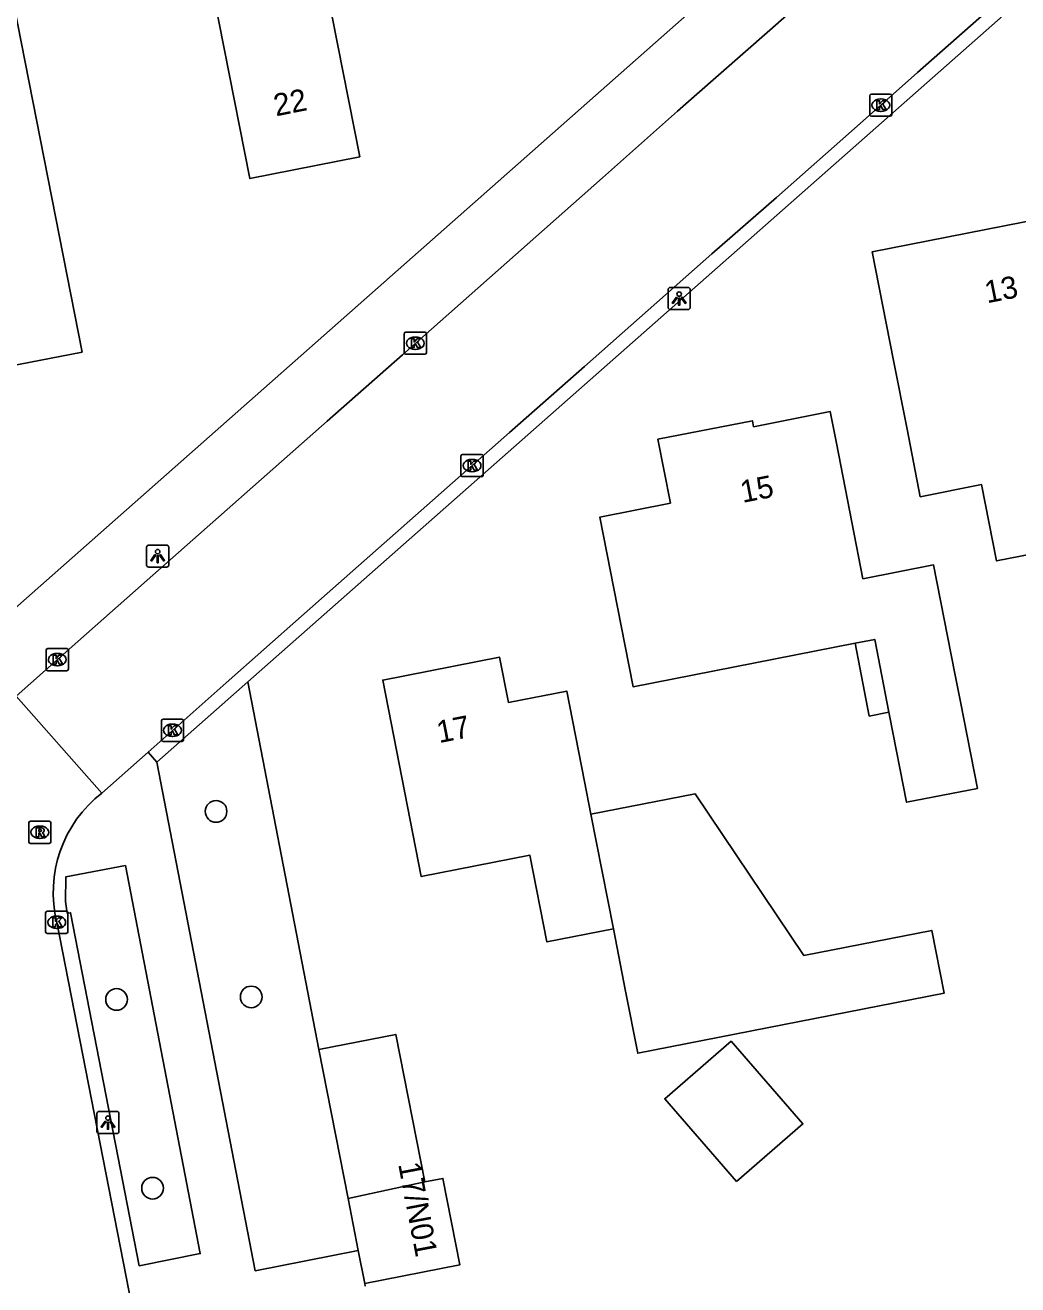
# Model space of a CAD drawing. Extents: x 157663 to 158496, y 379212 to 380934.
# Drawn here: x 158234.8 to 158279.6, y 380348.2 to 380405 of the extents above; entities that cross this region are included whole.
import ezdxf

# ---------------------------------------------------------------- set-up
doc = ezdxf.new("R2010")
doc.units = 0
for name, color, linetype in [('IMGEO_Boom', 7, 'Continuous'), ('IMGEO_Groenvoorziening', 7, 'Continuous'), ('IMGEO_Kolk', 7, 'Continuous'), ('IMGEO_Lichtpunt', 7, 'Continuous'), ('IMGEO_Pand', 7, 'Continuous'), ('IMGEO_Pand_nummerreeks', 7, 'Continuous'), ('IMGEO_Rijbaan_lokaal_open', 7, 'Continuous'), ('IMGEO_Rioolput', 7, 'Continuous'), ('IMGEO_Voetpad_open', 7, 'Continuous')]:
    doc.layers.add(name, color=color, linetype=linetype)

msp = doc.modelspace()

# ---------------------------------------------------------------- linework, layer by layer
at = {"layer": 'IMGEO_Boom'}
for centre in [(158243.442, 380369.576), (158238.959, 380361.095), (158245.027, 380361.208), (158240.581, 380352.586)]:
    msp.add_circle(centre, 0.489, dxfattribs=at)
at = {"layer": 'IMGEO_Groenvoorziening'}
msp.add_lwpolyline([(158248.079, 380358.837), (158244.872, 380375.418)], dxfattribs=at)
at = {"layer": 'IMGEO_Kolk'}
for p, q in [((158272.913, 380400.995), (158272.913, 380401.847)), ((158272.988, 380401.921), (158273.84, 380401.921)), ((158273.401, 380401.701), (158273.426, 380401.701)), ((158273.914, 380401.847), (158273.914, 380400.995)), ((158273.424, 380401.141), (158273.399, 380401.141)), ((158273.84, 380400.921), (158272.988, 380400.921)), ((158251.927, 380390.26), (158251.927, 380391.112)), ((158252.002, 380391.186), (158252.854, 380391.186)), ((158252.415, 380390.966), (158252.44, 380390.966)), ((158252.928, 380391.112), (158252.928, 380390.26)), ((158252.438, 380390.406), (158252.413, 380390.406)), ((158252.854, 380390.186), (158252.002, 380390.186)), ((158254.485, 380384.743), (158254.485, 380385.595)), ((158254.56, 380385.669), (158255.412, 380385.669)), ((158254.973, 380385.449), (158254.998, 380385.449)), ((158255.486, 380385.595), (158255.486, 380384.743)), ((158255.412, 380384.669), (158254.56, 380384.669)), ((158254.996, 380384.889), (158254.971, 380384.889)), ((158235.783, 380375.994), (158235.783, 380376.846)), ((158235.858, 380376.92), (158236.71, 380376.92)), ((158236.271, 380376.7), (158236.296, 380376.7)), ((158236.784, 380376.846), (158236.784, 380375.994)), ((158236.294, 380376.14), (158236.269, 380376.14)), ((158236.71, 380375.92), (158235.858, 380375.92)), ((158240.976, 380372.806), (158240.976, 380373.658)), ((158241.051, 380373.732), (158241.903, 380373.732)), ((158241.464, 380373.512), (158241.489, 380373.512)), ((158241.977, 380373.658), (158241.977, 380372.806)), ((158241.903, 380372.732), (158241.051, 380372.732)), ((158241.487, 380372.952), (158241.462, 380372.952)), ((158235.759, 380364.15), (158235.759, 380365.002)), ((158235.834, 380365.076), (158236.686, 380365.076)), ((158236.247, 380364.856), (158236.272, 380364.856)), ((158236.76, 380365.002), (158236.76, 380364.15)), ((158236.27, 380364.296), (158236.245, 380364.296)), ((158236.686, 380364.076), (158235.834, 380364.076))]:
    msp.add_line(p, q, dxfattribs=at)
for points in [[(158272.913, 380400.995), (158272.913, 380401.847)], [(158272.988, 380401.921), (158273.84, 380401.921)], [(158273.234, 380401.621), (158273.357, 380401.621), (158273.357, 380401.47), (158273.487, 380401.621), (158273.651, 380401.621), (158273.505, 380401.47), (158273.658, 380401.221), (158273.506, 380401.221), (158273.421, 380401.385), (158273.357, 380401.318), (158273.357, 380401.221), (158273.234, 380401.221), (158273.234, 380401.621)], [(158273.914, 380401.847), (158273.914, 380400.995)], [(158273.84, 380400.921), (158272.988, 380400.921)], [(158251.927, 380390.26), (158251.927, 380391.112)], [(158252.002, 380391.186), (158252.854, 380391.186)], [(158252.248, 380390.886), (158252.371, 380390.886), (158252.371, 380390.735), (158252.501, 380390.886), (158252.665, 380390.886), (158252.519, 380390.735), (158252.672, 380390.486), (158252.52, 380390.486), (158252.435, 380390.65), (158252.371, 380390.583), (158252.371, 380390.486), (158252.248, 380390.486), (158252.248, 380390.886)], [(158252.928, 380391.112), (158252.928, 380390.26)], [(158252.854, 380390.186), (158252.002, 380390.186)], [(158254.485, 380384.743), (158254.485, 380385.595)], [(158254.56, 380385.669), (158255.412, 380385.669)], [(158254.806, 380385.369), (158254.929, 380385.369), (158254.929, 380385.218), (158255.059, 380385.369), (158255.223, 380385.369), (158255.077, 380385.218), (158255.23, 380384.969), (158255.078, 380384.969), (158254.993, 380385.133), (158254.929, 380385.066), (158254.929, 380384.969), (158254.806, 380384.969), (158254.806, 380385.369)], [(158255.486, 380385.595), (158255.486, 380384.743)], [(158255.412, 380384.669), (158254.56, 380384.669)], [(158235.783, 380375.994), (158235.783, 380376.846)], [(158235.858, 380376.92), (158236.71, 380376.92)], [(158236.104, 380376.62), (158236.227, 380376.62), (158236.227, 380376.469), (158236.357, 380376.62), (158236.521, 380376.62), (158236.375, 380376.469), (158236.528, 380376.22), (158236.376, 380376.22), (158236.291, 380376.384), (158236.227, 380376.317), (158236.227, 380376.22), (158236.104, 380376.22), (158236.104, 380376.62)], [(158236.784, 380376.846), (158236.784, 380375.994)], [(158236.71, 380375.92), (158235.858, 380375.92)], [(158240.976, 380372.806), (158240.976, 380373.658)], [(158241.051, 380373.732), (158241.903, 380373.732)], [(158241.297, 380373.432), (158241.42, 380373.432), (158241.42, 380373.281), (158241.55, 380373.432), (158241.714, 380373.432), (158241.568, 380373.281), (158241.721, 380373.032), (158241.569, 380373.032), (158241.484, 380373.196), (158241.42, 380373.129), (158241.42, 380373.032), (158241.297, 380373.032), (158241.297, 380373.432)], [(158241.977, 380373.658), (158241.977, 380372.806)], [(158241.903, 380372.732), (158241.051, 380372.732)], [(158235.759, 380364.15), (158235.759, 380365.002)], [(158235.834, 380365.076), (158236.686, 380365.076)], [(158236.08, 380364.776), (158236.203, 380364.776), (158236.203, 380364.625), (158236.333, 380364.776), (158236.497, 380364.776), (158236.351, 380364.625), (158236.504, 380364.376), (158236.352, 380364.376), (158236.267, 380364.54), (158236.203, 380364.473), (158236.203, 380364.376), (158236.08, 380364.376), (158236.08, 380364.776)], [(158236.76, 380365.002), (158236.76, 380364.15)], [(158236.686, 380364.076), (158235.834, 380364.076)]]:
    msp.add_lwpolyline(points, dxfattribs=at)
for centre, start, end in [((158272.99, 380401.845), 91.552, 178.448), ((158272.99, 380401.845), 91.552, 178.448), ((158273.838, 380401.845), 1.552, 88.448), ((158273.838, 380401.845), 1.552, 88.448), ((158272.99, 380400.997), 181.552, 268.448), ((158272.99, 380400.997), 181.552, 268.448), ((158273.838, 380400.997), 271.552, 358.448), ((158273.838, 380400.997), 271.552, 358.448), ((158252.004, 380391.11), 91.552, 178.448), ((158252.004, 380391.11), 91.552, 178.448), ((158252.852, 380391.11), 1.552, 88.448), ((158252.852, 380391.11), 1.552, 88.448), ((158252.004, 380390.262), 181.552, 268.448), ((158252.004, 380390.262), 181.552, 268.448), ((158252.852, 380390.262), 271.552, 358.448), ((158252.852, 380390.262), 271.552, 358.448), ((158254.562, 380385.593), 91.552, 178.448), ((158254.562, 380385.593), 91.552, 178.448), ((158255.41, 380385.593), 1.552, 88.448), ((158255.41, 380385.593), 1.552, 88.448), ((158254.562, 380384.745), 181.552, 268.448), ((158254.562, 380384.745), 181.552, 268.448), ((158255.41, 380384.745), 271.552, 358.448), ((158255.41, 380384.745), 271.552, 358.448), ((158235.86, 380376.844), 91.552, 178.448), ((158235.86, 380376.844), 91.552, 178.448), ((158236.708, 380376.844), 1.552, 88.448), ((158236.708, 380376.844), 1.552, 88.448), ((158235.86, 380375.996), 181.552, 268.448), ((158235.86, 380375.996), 181.552, 268.448), ((158236.708, 380375.996), 271.552, 358.448), ((158236.708, 380375.996), 271.552, 358.448), ((158241.053, 380373.656), 91.552, 178.448), ((158241.053, 380373.656), 91.552, 178.448), ((158241.901, 380373.656), 1.552, 88.448), ((158241.901, 380373.656), 1.552, 88.448), ((158241.053, 380372.808), 181.552, 268.448), ((158241.053, 380372.808), 181.552, 268.448), ((158241.901, 380372.808), 271.552, 358.448), ((158241.901, 380372.808), 271.552, 358.448), ((158235.836, 380365), 91.552, 178.448), ((158235.836, 380365), 91.552, 178.448), ((158236.684, 380365), 1.552, 88.448), ((158236.684, 380365), 1.552, 88.448), ((158235.836, 380364.152), 181.552, 268.448), ((158235.836, 380364.152), 181.552, 268.448), ((158236.684, 380364.152), 271.552, 358.448), ((158236.684, 380364.152), 271.552, 358.448)]:
    msp.add_arc(centre, 0.0765, start, end, dxfattribs=at)
for centre, major_axis, ratio, start_param, end_param in [((158273.4, 380401.421), (-0.387, 0.002), 0.722429, 4.712389, 7.853982), ((158273.425, 380401.421), (-0.39, 0.002), 0.717154, 1.570796, 4.712389), ((158252.414, 380390.686), (-0.387, 0.002), 0.722429, 4.712389, 7.853982), ((158252.439, 380390.686), (-0.39, 0.002), 0.717154, 1.570796, 4.712389), ((158254.972, 380385.169), (-0.387, 0.002), 0.722429, 4.712389, 7.853982), ((158254.997, 380385.169), (-0.39, 0.002), 0.717154, 1.570796, 4.712389), ((158236.27, 380376.42), (-0.387, 0.002), 0.722429, 4.712389, 7.853982), ((158236.295, 380376.42), (-0.39, 0.002), 0.717154, 1.570796, 4.712389), ((158241.463, 380373.232), (-0.387, 0.002), 0.722429, 4.712389, 7.853982), ((158241.488, 380373.232), (-0.39, 0.002), 0.717154, 1.570796, 4.712389), ((158236.246, 380364.576), (-0.387, 0.002), 0.722429, 4.712389, 7.853982), ((158236.271, 380364.576), (-0.39, 0.002), 0.717154, 1.570796, 4.712389)]:
    msp.add_ellipse(centre, major_axis=major_axis, ratio=ratio, start_param=start_param, end_param=end_param, dxfattribs=at)
at = {"layer": 'IMGEO_Lichtpunt'}
for p, q in [((158263.823, 380393.106), (158263.823, 380392.299)), ((158263.823, 380393.106), (158263.823, 380392.299)), ((158264.725, 380393.201), (158263.917, 380393.201)), ((158264.725, 380393.201), (158263.917, 380393.201)), ((158264.819, 380392.299), (158264.819, 380393.106)), ((158264.819, 380392.299), (158264.819, 380393.106)), ((158263.917, 380392.205), (158264.725, 380392.205)), ((158263.917, 380392.205), (158264.725, 380392.205)), ((158240.312, 380381.49), (158240.312, 380380.683)), ((158240.312, 380381.49), (158240.312, 380380.683)), ((158241.214, 380381.585), (158240.406, 380381.585)), ((158241.214, 380381.585), (158240.406, 380381.585)), ((158241.308, 380380.683), (158241.308, 380381.49)), ((158241.308, 380380.683), (158241.308, 380381.49)), ((158240.406, 380380.589), (158241.214, 380380.589)), ((158240.406, 380380.589), (158241.214, 380380.589)), ((158238.069, 380355.951), (158238.069, 380355.144)), ((158238.069, 380355.951), (158238.069, 380355.144)), ((158238.971, 380356.046), (158238.163, 380356.046)), ((158238.971, 380356.046), (158238.163, 380356.046)), ((158239.065, 380355.144), (158239.065, 380355.951)), ((158239.065, 380355.144), (158239.065, 380355.951)), ((158238.163, 380355.05), (158238.971, 380355.05)), ((158238.163, 380355.05), (158238.971, 380355.05))]:
    msp.add_line(p, q, dxfattribs=at)
for points in [[(158264.197, 380392.77), (158264.236, 380392.742), (158264.048, 380392.48), (158264.01, 380392.507), (158264.197, 380392.77)], [(158264.299, 380392.722), (158264.346, 380392.722), (158264.346, 380392.4), (158264.299, 380392.4), (158264.299, 380392.722)], [(158264.409, 380392.742), (158264.447, 380392.769), (158264.634, 380392.507), (158264.595, 380392.479), (158264.409, 380392.742)], [(158240.686, 380381.154), (158240.725, 380381.126), (158240.537, 380380.864), (158240.499, 380380.891), (158240.686, 380381.154)], [(158240.898, 380381.126), (158240.936, 380381.153), (158241.123, 380380.891), (158241.084, 380380.863), (158240.898, 380381.126)], [(158240.788, 380381.106), (158240.835, 380381.106), (158240.835, 380380.784), (158240.788, 380380.784), (158240.788, 380381.106)], [(158238.443, 380355.615), (158238.482, 380355.587), (158238.294, 380355.325), (158238.256, 380355.352), (158238.443, 380355.615)], [(158238.655, 380355.587), (158238.693, 380355.614), (158238.88, 380355.352), (158238.841, 380355.324), (158238.655, 380355.587)], [(158238.545, 380355.567), (158238.592, 380355.567), (158238.592, 380355.245), (158238.545, 380355.245), (158238.545, 380355.567)]]:
    msp.add_lwpolyline(points, dxfattribs=at)
for centre in [(158264.322, 380392.904), (158240.811, 380381.288), (158238.568, 380355.749)]:
    msp.add_circle(centre, 0.0994, dxfattribs=at)
for centre, start, end in [((158263.917, 380393.106), 90, 180), ((158263.917, 380393.106), 90, 180), ((158264.725, 380393.106), 0, 90), ((158264.725, 380393.106), 0, 90), ((158263.917, 380392.299), 180, 270), ((158263.917, 380392.299), 180, 270), ((158264.725, 380392.299), 270, 0), ((158264.725, 380392.299), 270, 360), ((158240.406, 380381.49), 90, 180), ((158240.406, 380381.49), 90, 180), ((158241.214, 380381.49), 0, 90), ((158241.214, 380381.49), 0, 90), ((158240.406, 380380.683), 180, 270), ((158240.406, 380380.683), 180, 270), ((158241.214, 380380.683), 270, 0), ((158241.214, 380380.683), 270, 360), ((158238.163, 380355.951), 90, 180), ((158238.163, 380355.951), 90, 180), ((158238.971, 380355.951), 0, 90), ((158238.971, 380355.951), 0, 90), ((158238.163, 380355.144), 180, 270), ((158238.163, 380355.144), 180, 270), ((158238.971, 380355.144), 270, 0), ((158238.971, 380355.144), 270, 360)]:
    msp.add_arc(centre, 0.0946, start, end, dxfattribs=at)
at = {"layer": 'IMGEO_Pand'}
for points in [[(158249.925, 380399.091), (158244.97, 380398.113), (158242.653, 380409.853), (158237.91, 380408.917), (158236.214, 380417.513), (158240.957, 380418.449), (158240.721, 380419.647), (158245.675, 380420.625), (158249.925, 380399.091)], [(158237.414, 380390.287), (158234.076, 380389.629), (158233.471, 380392.692), (158224.197, 380390.862), (158222.248, 380400.737), (158229.867, 380402.241), (158229.329, 380404.968), (158234.322, 380405.953), (158237.414, 380390.287)], [(158273.989, 380389.906), (158274.597, 380386.804), (158275.193, 380383.761), (158277.958, 380384.309), (158278.632, 380380.869), (158286.286, 380382.369), (158286.621, 380380.658), (158289.949, 380381.31), (158288.978, 380386.265), (158288.016, 380391.171), (158284.876, 380390.555), (158283.558, 380396.876), (158279.838, 380396.147), (158273.027, 380394.812), (158273.989, 380389.906)], [(158273.783, 380374.05), (158273.813, 380373.897), (158274.578, 380369.99), (158277.771, 380370.615), (158277.004, 380374.523), (158276.756, 380375.786), (158275.795, 380380.692), (158272.61, 380380.068), (158271.412, 380386.179), (158271.133, 380387.601), (158267.676, 380386.923), (158267.623, 380387.193), (158263.365, 380386.358), (158263.931, 380383.474), (158260.748, 380382.85), (158261.71, 380377.944), (158262.249, 380375.195), (158272.251, 380377.156)], [(158273.783, 380374.05), (158273.141, 380377.33), (158272.251, 380377.156)], [(158272.251, 380377.156), (158272.893, 380373.876), (158273.783, 380374.05)], [(158260.341, 380369.449), (158260.052, 380370.929), (158259.252, 380375.003), (158256.622, 380374.488), (158256.223, 380376.528), (158250.956, 380375.496), (158252.692, 380366.639), (158257.597, 380367.6), (158258.363, 380363.689), (158261.355, 380364.275)], [(158261.355, 380364.275), (158261.904, 380361.471), (158262.453, 380358.667), (158276.266, 380361.372), (158275.71, 380364.21), (158269.95, 380363.083), (158265.042, 380370.371), (158260.341, 380369.449)], [(158260.341, 380369.449), (158261.355, 380364.275)], [(158252.849, 380352.869), (158251.546, 380359.517), (158248.079, 380358.837)], [(158266.903, 380352.888), (158269.9, 380355.485), (158266.667, 380359.214), (158263.671, 380356.617), (158266.903, 380352.888)], [(158248.079, 380358.837), (158249.395, 380352.122)], [(158249.395, 380352.122), (158252.849, 380352.869)], [(158250.145, 380348.294), (158254.438, 380349.135), (158253.674, 380353.03), (158252.849, 380352.869)], [(158249.395, 380352.122), (158249.854, 380349.782)], [(158249.854, 380349.782), (158250.145, 380348.294)]]:
    msp.add_lwpolyline(points, dxfattribs=at)
at = {"layer": 'IMGEO_Rijbaan_lokaal_open'}
for points in [[(158240.377, 380372.25), (158243.899, 380375.374), (158247.291, 380378.383), (158256.668, 380386.653), (158260.048, 380389.643), (158265.799, 380394.72), (158268.71, 380397.255), (158272.487, 380400.59), (158275.064, 380402.899), (158280.349, 380407.546), (158283.753, 380410.559), (158293.144, 380418.837), (158296.552, 380421.825), (158297.311, 380422.499), (158300.184, 380425.29)], [(158290.558, 380424.363), (158280.432, 380415.427), (158277.036, 380412.427), (158268.418, 380404.808), (158265.005, 380401.815), (158264.255, 380401.144), (158260.861, 380398.145), (158251.843, 380390.163), (158248.452, 380387.176), (158240.599, 380380.224), (158237.209, 380377.235), (158234.426, 380374.771)], [(158234.426, 380374.771), (158238.294, 380370.403)], [(158238.294, 380370.403), (158240.377, 380372.25)], [(158243.939, 380325.292), (158236.26, 380364.576)]]:
    msp.add_lwpolyline(points, dxfattribs=at)
msp.add_arc((158241.782, 380365.917), 5.682, 127.8634, 193.652, dxfattribs=at)
at = {"layer": 'IMGEO_Rioolput'}
for p, q in [((158234.996, 380368.207), (158234.996, 380369.059)), ((158235.071, 380369.133), (158235.923, 380369.133)), ((158235.484, 380368.913), (158235.509, 380368.913)), ((158235.997, 380369.059), (158235.997, 380368.207)), ((158235.923, 380368.133), (158235.071, 380368.133)), ((158235.507, 380368.353), (158235.482, 380368.353))]:
    msp.add_line(p, q, dxfattribs=at)
for points in [[(158234.996, 380368.207), (158234.996, 380369.059)], [(158235.071, 380369.133), (158235.923, 380369.133)], [(158235.585, 380368.831), (158235.333, 380368.833), (158235.333, 380368.433)], [(158235.511, 380368.752), (158235.457, 380368.752), (158235.457, 380368.671)], [(158235.457, 380368.671), (158235.509, 380368.671)], [(158235.997, 380369.059), (158235.997, 380368.207)], [(158235.923, 380368.133), (158235.071, 380368.133)], [(158235.333, 380368.433), (158235.457, 380368.433), (158235.457, 380368.595), (158235.468, 380368.595)], [(158235.515, 380368.566), (158235.586, 380368.433), (158235.726, 380368.433), (158235.661, 380368.559)]]:
    msp.add_lwpolyline(points, dxfattribs=at)
for centre, radius, start, end in [((158235.073, 380369.057), 0.0765, 91.552, 178.448), ((158235.073, 380369.057), 0.0765, 91.552, 178.448), ((158235.493, 380368.86), 0.19, 274.7715, 282.9687), ((158235.517, 380368.656), 0.0964, 77.0061, 93.1865), ((158235.531, 380368.713), 0.0378, 276.6634, 79.6772), ((158235.584, 380368.721), 0.109, 350.3612, 89.416), ((158235.582, 380368.721), 0.112, 277.5842, 350.9817), ((158235.921, 380369.057), 0.0765, 1.552, 88.448), ((158235.921, 380369.057), 0.0765, 1.552, 88.448), ((158235.073, 380368.209), 0.0765, 181.552, 268.448), ((158235.073, 380368.209), 0.0765, 181.552, 268.448), ((158235.467, 380368.542), 0.0533, 26.0293, 88.6989), ((158235.566, 380368.506), 0.108, 29.5134, 73.7905), ((158235.921, 380368.209), 0.0765, 271.552, 358.448), ((158235.921, 380368.209), 0.0765, 271.552, 358.448)]:
    msp.add_arc(centre, radius, start, end, dxfattribs=at)
for centre, major_axis, ratio, start_param, end_param in [((158235.483, 380368.633), (-0.387, 0.002), 0.722429, 4.712389, 7.853982), ((158235.508, 380368.633), (-0.39, 0.002), 0.717154, 1.570796, 4.712389)]:
    msp.add_ellipse(centre, major_axis=major_axis, ratio=ratio, start_param=start_param, end_param=end_param, dxfattribs=at)
at = {"layer": 'IMGEO_Voetpad_open'}
for points in [[(158292.091, 380429.371), (158279.605, 380418.293), (158279.393, 380418.507), (158278.773, 380417.976), (158275.266, 380414.885), (158268.406, 380408.809), (158233.333, 380377.826)], [(158244.872, 380375.418), (158297.805, 380422.134), (158299.264, 380423.498), (158303.395, 380427.849)], [(158240.774, 380371.801), (158244.872, 380375.418)], [(158240.377, 380372.25), (158240.774, 380371.801)], [(158240.774, 380371.801), (158245.202, 380348.864), (158249.854, 380349.782)], [(158239.364, 380367.138), (158236.673, 380366.625), (158236.648, 380365.507), (158236.736, 380364.985), (158236.884, 380365.007), (158239.982, 380349.091), (158242.731, 380349.638), (158239.364, 380367.138)], [(158250.145, 380348.294), (158250.171, 380348.164)]]:
    msp.add_lwpolyline(points, dxfattribs=at)

# ---------------------------------------------------------------- texts
at = {"layer": 'IMGEO_Pand_nummerreeks'}
for s, rotation, p in [('22', 11.1653, (158246.146, 380400.914)), ('13', 11.089, (158278.202, 380392.483)), ('15', 11.0982, (158267.186, 380383.484)), ('17', 11.0867, (158253.498, 380372.651)), ('17/N01', 280.8016, (158251.652, 380353.671))]:
    msp.add_text(s, height=1, rotation=rotation, dxfattribs=at).set_placement(p)

doc.saveas('drawing.dxf')
